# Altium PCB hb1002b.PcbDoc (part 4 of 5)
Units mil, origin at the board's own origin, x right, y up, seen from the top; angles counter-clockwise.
Board outline 2756 x 3549 mil, 2 copper layers (Top Layer, Bottom Layer); 120 components, 136 nets, 498 pads, 328 vias.
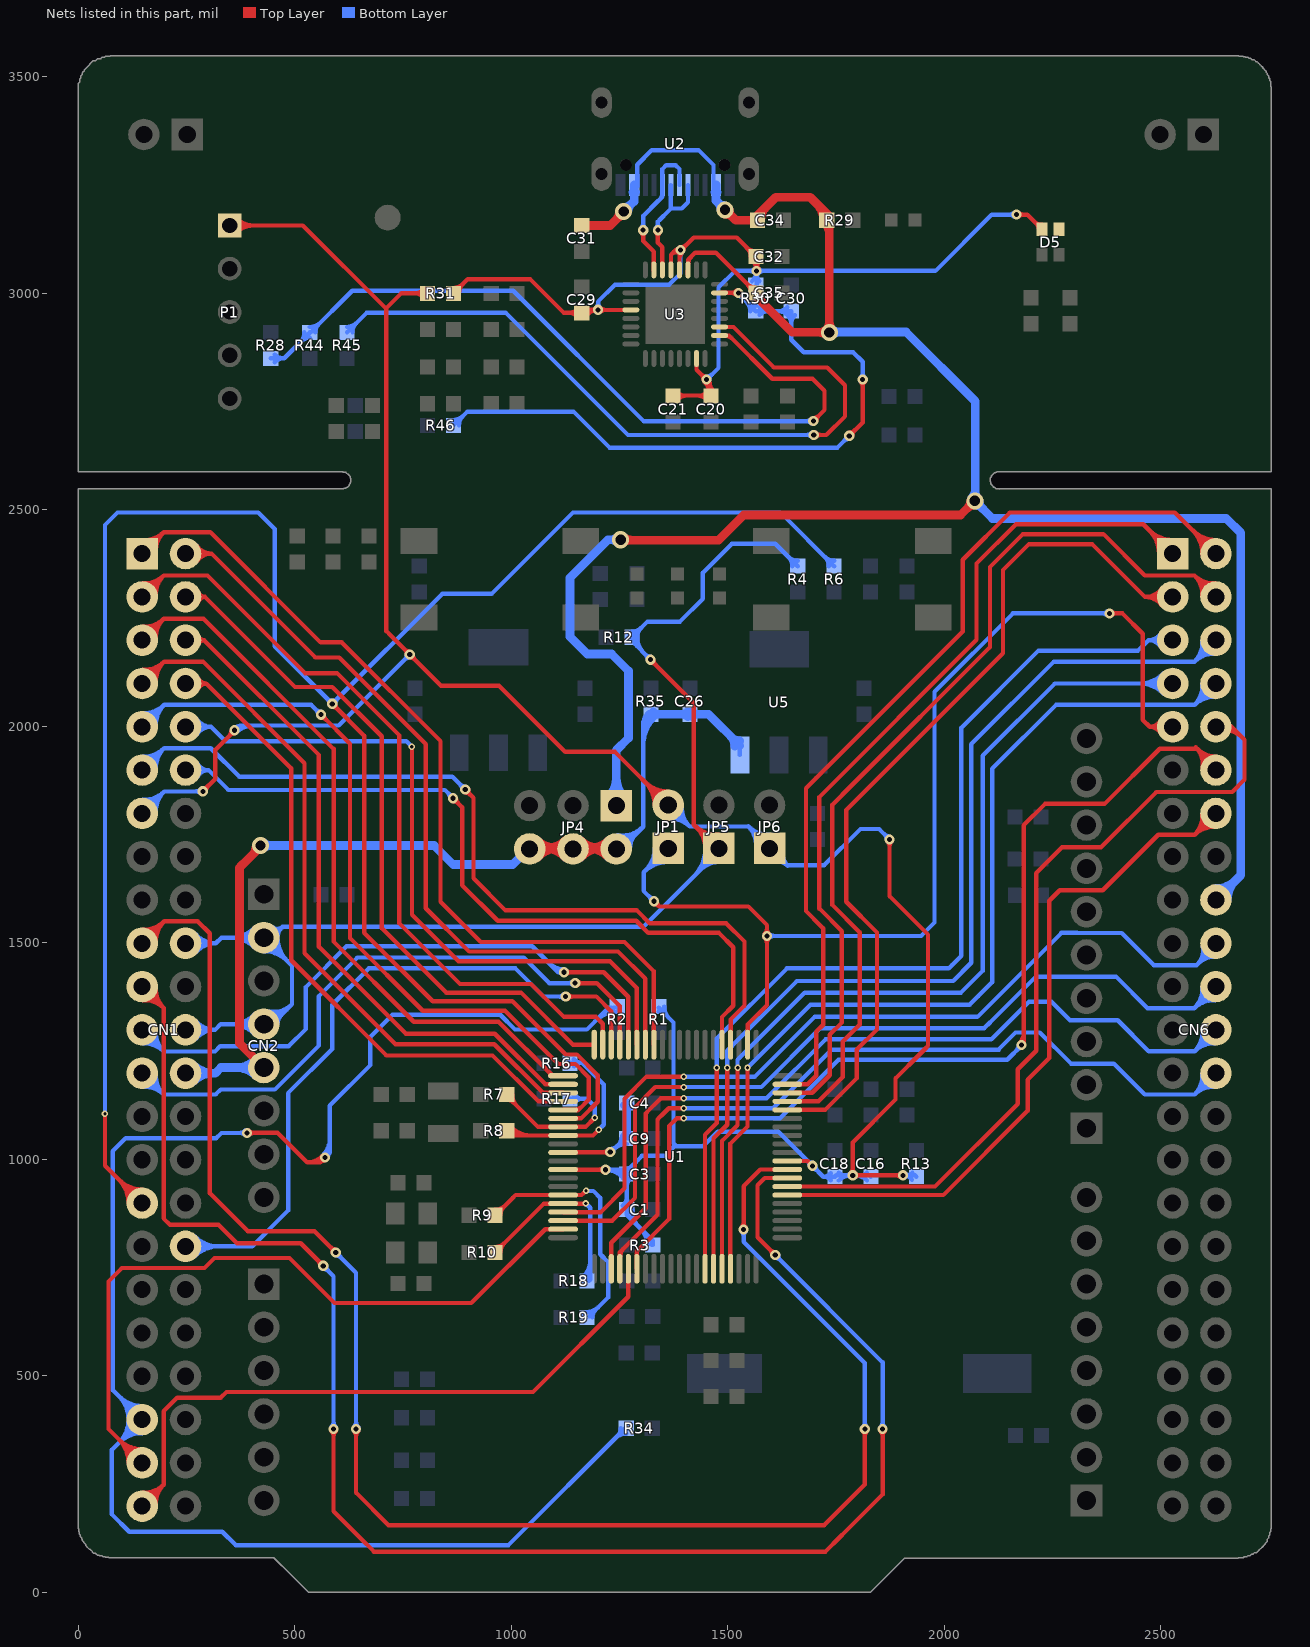
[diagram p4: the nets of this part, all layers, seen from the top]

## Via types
v1: diameter 23.62, hole 11.81, Top Layer to Bottom Layer, tented both sides, 276 vias
v2: diameter 39.37, hole 23.62, Top Layer to Bottom Layer, tented both sides, 27 vias
v3: diameter 15, hole 8, Top Layer to Bottom Layer, tented both sides, 25 vias

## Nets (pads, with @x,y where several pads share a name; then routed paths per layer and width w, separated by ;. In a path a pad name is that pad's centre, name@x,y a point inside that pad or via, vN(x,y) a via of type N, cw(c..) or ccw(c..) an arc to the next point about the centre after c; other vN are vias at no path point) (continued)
PC0: CN6.20 U1.17 | length 2102
  Top Layer w10: U1.17@1120.14,878.05 1120.69,877.5 1206.5,877.5 1262,933 1262,1140 1313,1191 v3(1399,1191)
  Bottom Layer w10: v3@1400,1191 1563,1191 1701,1329 2077,1329 2271,1523 2307.94,1523 2308.36,1522.58 2410.42,1522.58 2484.58,1448.42 2582.88,1448.42 2628,1493.54 CN6.20@2628,1499 ; CN6.20@2597.37,1492 cw(c2554.54,1482.22) 2585.61,1451.15 cw(c2625.38,1411.38) CN6.20@2627.06,1467.6 ; 2598.4,1463.94 ccw(c2575.36,1486.97) CN6.20@2607.12,1494.23 ; 2601.98,1467.52 cw(c2626.33,1443.18) CN6.20@2627.36,1477.59
PC1: CN6.22 U1.18 | length 2111.7
  Top Layer w10: U1.18@1120.14,858.36 1233.36,858.36 1286,911 1286,1120 1333,1167 v3(1399,1167)
  Bottom Layer w10: v3@1400,1167 1578,1167 1714,1303 2093,1303 2114,1324 ; 2101,1311 2114,1324 ; CN6.22@2596.62,1397.4 cw(c2532.85,1394.16) 2578,1349 ; CN6.22@2606.61,1397.91 cw(c2563.13,1395.7) 2593.92,1364.92 cw(c2624.7,1334.13) CN6.22@2626.91,1377.61 ; CN6.22@2626.4,1367.62 ccw(c2623.16,1303.85) 2578,1349 ; CN6.22@2628,1399 2578,1349 ; 2114,1324 2212,1422 2397,1422 2470,1349 2578,1349
PC2: CN1.43 U1.19 | length 1838
  Top Layer w10: CN1.43@116.58,299 ccw(c40.73,299) 94.37,352.63 ccw(c148,406.27) CN1.43@148,330.42 ; CN1.43@126.58,299 ccw(c74.88,299) 111.44,335.56 ccw(c148,372.12) CN1.43@148,320.42 ; CN1.43@148,299 70,377 70,718 101,749 292,749 315,772 488,772 592,668 908,668 1078.68,838.68 U1.19@1120.14,838.68
PC3: CN6.24 U1.23 | length 2075
  Top Layer w10: U1.23@1231.36,747.14 1231.36,807.36 1311,887 1311,1106 ; 1313,1108 1346,1141 v3@1398,1141
  Bottom Layer w10: v3@1400,1141 1562,1141 ; 1582,1141 1562,1141 ; CN6.24@2596.64,1297.13 cw(c2534.73,1293.44) 2578.58,1249.58 ; CN6.24@2606.62,1297.72 cw(c2564.42,1295.21) 2594.31,1265.31 cw(c2624.21,1235.42) CN6.24@2626.72,1277.62 ; CN6.24@2626.13,1267.64 ccw(c2622.44,1205.73) 2578.58,1249.58 ; CN6.24@2628,1299 2578.58,1249.58 ; 1562,1141 1590,1141 1726,1277 2109,1277 2196,1364 2248,1364 2291,1321 2401,1321 2472.42,1249.58 2578.58,1249.58
  other v3: 1399,1141
PC4: CN6.26 U1.24 | length 2161
  Top Layer w10: U1.24@1251.05,747.14 1251.05,785.05 1338,872 1338,946 ; U1.24@1251.95,775.69 cw(c1276.74,775.69) 1259.21,793.21 ; 1338,874 1338,946 ; 1340,1094 1353.5,1107.5 ; v3@1398,1118 1364,1118 1353.5,1107.5 ; 1338,946 1338,1092 1353.5,1107.5
  Bottom Layer w10: v3(1399,1118) 1557,1118 ; 1599,1118 1557,1118 ; 2127,1253 1740,1253 1605,1118 1557,1118 ; 2127,1255 2165,1293 2221,1293 2293,1221 2392,1221 2463.42,1149.58 2578.58,1149.58 ; CN6.26@2596.64,1197.13 cw(c2534.73,1193.44) 2578.58,1149.58 ; CN6.26@2606.62,1197.72 cw(c2564.42,1195.21) 2594.31,1165.31 cw(c2624.21,1135.42) CN6.26@2626.72,1177.62 ; CN6.26@2626.13,1167.64 ccw(c2622.44,1105.73) 2578.58,1149.58 ; CN6.26@2628,1199 2578.58,1149.58
PC5: CN1.45 U1.25 | length 1663.3
  Top Layer w10: CN1.45@148,199 197.42,248.42 ; CN1.45@149.28,220.38 ccw(c151.79,262.58) 181.69,232.69 ccw(c211.58,202.79) CN1.45@169.38,200.28 ; CN1.45@149.87,230.36 ccw(c153.56,292.27) 197.42,248.42 ; CN1.45@179.36,200.87 cw(c241.27,204.56) 197.42,248.42 ; U1.25@1270.73,747.14 1270.73,682.73 1050.58,462.58 342.58,462.58 329.58,449.58 228.7,449.58 197.42,418.3 197.42,248.42
PC6: CN6.12 U1.26 | length 2522.7
  Top Layer w10: U1.26@1290.42,747.14 1290.42,787.42 1365,862 1365,1077 1383,1095 v3@1398,1095 ; v1@2174.18,1268.82 ccw(c2150.49,1292.51) 2184,1292.51 ; v1(2179,1264) 2184,1269 2184,1772 2233,1821 2370.58,1821 2498,1948.42 2584.58,1948.42 ; 2581.58,1951.42 cw(c2542.77,1912.6) CN6.12@2596.98,1903.95 ; 2595.44,1937.56 cw(c2566.67,1908.79) CN6.12@2606.85,1902.38 ; 2601.68,1931.32 ccw(c2628,1957.64) CN6.12@2628,1920.42 ; CN6.12@2628,1899 2628,1905 2584.58,1948.42 ; CN6.12@2628,1930.42 cw(c2628,1991.78) 2584.61,1948.39
  Bottom Layer w10: v3(1399,1095) 1621,1095 1756,1230 2146,1230 2179,1263 v1(2179,1264) ; 2166.67,1250.67 ccw(c2153.33,1264) v1@2172.19,1264 ; 2169.08,1253.08 cw(c2179,1243.16) v1@2179,1257.19
PC7: CN6.14 U1.46 | length 1791.8
  Top Layer w10: U1.46@1637.86,917.42 1882,917.42 1921,917.42 ; 1926.42,917.42 1921,917.42 ; CN6.14@2596.64,1797.13 cw(c2534.73,1793.44) 2578.58,1749.58 ; CN6.14@2606.62,1797.72 cw(c2564.42,1795.21) 2594.31,1765.31 cw(c2624.21,1735.42) CN6.14@2626.72,1777.62 ; CN6.14@2626.13,1767.64 ccw(c2622.44,1705.73) 2578.58,1749.58 ; CN6.14@2628,1799 2578.58,1749.58 ; 1921,917.42 1998.42,917.42 2193,1112 2193,1184 2243,1234 2243,1597 2267.42,1621.42 2366.42,1621.42 2494.58,1749.58 2578.58,1749.58
PC8: CN6.10 U1.47 | length 2110.2
  Top Layer w10: U1.47@1637.86,937.1 1877,937.1 ; 1890,937.1 1877,937.1 ; 2274.58,1720.58 2292,1720.58 ; 2349.58,1720.58 2331,1720.58 ; CN6.10@2625.39,2007.18 cw(c2637.48,1969.32) 2665.58,1997.42 ; CN6.10@2628,1999 2664,1999 2694,1969 2694,1877 2665.42,1848.42 2490.42,1848.42 2362.58,1720.58 2331,1720.58 ; CN6.10@2628.43,1997.65 cw(c2643.1,1951.73) 2677.18,1985.82 ; CN6.10@2631.47,1988.12 cw(c2648.72,1934.14) 2688.79,1974.21 ; 1877,937.1 1979.1,937.1 2170,1128 2170,1208 2213,1251 2213,1661 2272.58,1720.58 2292,1720.58 ; 2292,1720.58 2331,1720.58
PC9: CN6.9 JP1.1 U1.62 | length 2960.7
  Top Layer w10: v1@1330,1589.19 cw(c1330,1572.75) 1341.63,1584.37 cw(c1353.25,1596) v1@1336.81,1596 ; v1(1330,1596) 1342,1584 1548,1584 1591,1541 v1(1591,1516) v1@1591,1511 ; U1.62@1546.32,1264.86 1546.32,1311.32 1591,1356 v1@1591,1510 ; v1@1586.18,1511.18 cw(c1574.56,1499.56) 1591,1499.56 cw(c1607.44,1499.56) v1@1595.82,1511.18 ; v1@1586.18,1520.82 ccw(c1574.56,1532.44) 1591,1532.44 ccw(c1607.44,1532.44) v1@1595.82,1520.82 ; v1(2382,2261) 2412,2261 2459,2214 2459,2015 2475,1999 ; v1@2386.82,2256.18 cw(c2398.44,2244.56) 2398.44,2261 cw(c2398.44,2277.44) v1@2386.82,2265.82 ; CN6.9@2500.44,1983.92 ccw(c2475,1970.01) 2475,1999 ; CN6.9@2500.44,2014.08 cw(c2475,2027.99) 2475,1999 ; CN6.9@2528,1999 2475,1999
  Bottom Layer w10: 1305.95,1662.95 cw(c1363,1605.91) JP1.1@1363,1686.58 ; 1310.78,1667.78 ccw(c1260.56,1718) JP1.1@1331.58,1718 ; 1323.02,1680.02 cw(c1363,1640.05) JP1.1@1363,1696.58 ; v1@1323.19,1596 ccw(c1306.75,1596) 1318.37,1607.63 ccw(c1330,1619.25) v1@1330,1602.81 ; JP1.1@1327.85,1684.85 ccw(c1294.71,1718) JP1.1@1341.58,1718 ; v1(1330,1596) 1306,1620 1306,1663 JP1.1@1362,1719 ; v1@1590,1516 v1(1591,1516) 1947,1516 1978,1547 1978,2080 2159,2261 v1(2382,2261) ; v1@1595.82,1511.18 cw(c1607.44,1499.56) 1607.44,1516 cw(c1607.44,1532.44) v1@1595.82,1520.82 ; v1@2377.18,2256.18 ccw(c2365.56,2244.56) 2365.56,2261 ccw(c2365.56,2277.44) v1@2377.18,2265.82
PC10: CN1.11 U1.64 | length 2191.9
  Top Layer w10: v1@894,1847.19 cw(c894,1830.75) 905.63,1842.37 cw(c917.25,1854) v1@900.81,1854 ; v1(894,1854) 913,1835 913,1649 987,1575 1290.46,1575 1320.46,1545 1497,1545 1539,1503 1539,1355.09 1506.95,1323.04 U1.64@1506.95,1264.86
  Bottom Layer w10: CN1.11@148,1899 198.58,1949.58 ; CN1.11@148.91,1920.4 ccw(c150.8,1965.16) 182.48,1933.48 ccw(c214.16,1901.8) CN1.11@169.4,1899.91 ; CN1.11@149.33,1930.39 ccw(c152.11,1996.05) 198.58,1949.58 ; CN1.11@179.39,1900.33 cw(c245.05,1903.11) 198.58,1949.58 ; v1@887.19,1854 ccw(c870.75,1854) 882.37,1865.63 ccw(c894,1877.25) v1@894,1860.81 ; v1(894,1854) 864.37,1883.63 372.37,1883.63 306.42,1949.58 198.58,1949.58
PC11: CN1.12 U1.65 | length 1889.4
  Top Layer w10: v1@866,1827.19 cw(c866,1810.75) 877.63,1822.37 cw(c889.25,1834) v1@872.81,1834 ; v1(866,1834) 886.81,1813.19 886.81,1633.19 969,1551 1289,1551 1317,1523 1480,1523 1513,1490 1513,1354.54 1487.27,1328.81 U1.65@1487.27,1264.86
  Bottom Layer w10: CN1.12@248,1899 301,1899 ; CN1.12@275.56,1883.92 cw(c301,1870.01) 301,1899 ; CN1.12@275.56,1914.08 ccw(c301,1927.99) 301,1899 ; v1@859.19,1834 ccw(c842.75,1834) 854.37,1845.63 ccw(c866,1857.25) v1@866,1840.81 ; v1(866,1834) 847,1853 347,1853 301,1899
PC12: CN1.9 U1.5 | length 2047.9
  Top Layer w10: v1@561,2020.19 cw(c561,2003.75) 572.63,2015.37 cw(c584.25,2027) v1@567.81,2027 ; v1@562,2026 628,1960 628,1511 796,1343 986,1343 1109,1220 1148.43,1220 1179,1189.43 1179,1137.53 1156.52,1115.05 ; U1.5@1120.14,1114.27 1120.92,1115.05 1156.52,1115.05 ; U1.5@1148.69,1115.17 ccw(c1148.69,1134.38) 1162.27,1120.8 ; U1.5@1149.3,1114.93 ccw(c1152.85,1118.71) 1156.52,1115.05
  Bottom Layer w10: CN1.9@148,1999 198.58,2049.58 ; CN1.9@148.91,2020.4 ccw(c150.8,2065.16) 182.48,2033.48 ccw(c214.16,2001.8) CN1.9@169.4,1999.91 ; CN1.9@149.33,2030.39 ccw(c152.11,2096.05) 198.58,2049.58 ; CN1.9@179.39,2000.33 cw(c245.05,2003.11) 198.58,2049.58 ; v1@554.19,2027 ccw(c537.75,2027) 549.37,2038.63 ccw(c561,2050.25) v1@561,2033.81 ; v1(561,2027) 538.42,2049.58 198.58,2049.58
PC13: CN1.31 R6.1 U1.6 | length 5649.8
  Top Layer w10: v3@62,1104 62,985 CN1.31@148,899 ; CN1.31@116.58,899 ccw(c40.73,899) 94.37,952.63 ccw(c148,1006.27) CN1.31@148,930.42 ; CN1.31@126.58,899 ccw(c74.88,899) 111.44,935.56 ccw(c148,972.12) CN1.31@148,920.42 ; v1@587,2045.19 cw(c587,2028.75) 598.63,2040.37 cw(c610.25,2052) v1@593.81,2052 ; v1(587,2052) 661,1978 661,1885 ; 661,1945 661,1885 ; U1.6@1120.14,1094.58 1161.51,1094.58 1200,1133.08 1200,1193.89 1151.89,1242 1126,1242 1003,1365 819,1365 661,1523 661,1885
  Bottom Layer w10: v3(62,1104.99) 62,2465 91,2494 416,2494 454,2456 454,2185 v1(587,2052) 841,2306 955,2306 1143,2494 1622,2494 R6.1@1746,2370 ; v1@580.19,2052 ccw(c563.75,2052) 575.37,2063.63 ccw(c587,2075.25) 587,2058.81 ccw(c587,2075.25) 598.63,2063.63 ccw(c610.25,2052) v1@593.81,2052 ; R6.1@1733.5,2370 ccw(c1703.32,2370) 1724.66,2391.34 ccw(c1746,2412.68) R6.1@1746,2382.5
PC14: R7.1 R17.2 U1.7 | length 425.9
  Top Layer w10: R7.1@990,1137.5 cw(c990,1114.82) 1006.04,1130.86 ; R7.1@993.9,1143 1062,1074.9 U1.7@1120.14,1074.9 1171.9,1074.9 v3@1192,1095 ; R7.1@1002.5,1150 ccw(c1040.17,1150) 1013.53,1123.36
  Bottom Layer w10: R17.2@1129,1137 R17.2@1136,1137 ; R17.2@1136,1140 1175,1140 1193,1122 v3@1193,1097 ; R17.2@1144.84,1131.16 cw(c1166.18,1109.82) 1166.18,1140 cw(c1166.18,1170.18) R17.2@1144.84,1148.84
  other v3: 1193,1096
PC15: R8.1 R16.2 U1.8 | length 570.2
  Top Layer w10: R8.1@990.21,1055.21 U1.8@1120.14,1055.21 1159,1055.21 ; R8.1@991.77,1067.77 ccw(c1022.08,1098.08) 1022.08,1055.21 ; R8.1@998.84,1074.84 ccw(c1046.22,1122.22) 1046.22,1055.21 ; 1169.21,1055.21 1159,1055.21 ; v3(1202,1068) 1189.21,1055.21 1159,1055.21
  Bottom Layer w10: R16.2@1130,1223 1132,1223 1164,1223 ; R16.2@1144.84,1230.84 ccw(c1163.76,1249.76) 1163.76,1223 ; R16.2@1145.78,1214.22 cw(c1164,1199.72) 1164,1223 ; v3(1202,1068) 1214,1080 1214,1173 1164,1223
PD0: CN1.21 U1.48 | length 4302.2
  Top Layer w10: CN1.21@148,1399 197.42,1349.58 ; CN1.21@149.28,1377.62 cw(c151.79,1335.42) 181.69,1365.31 cw(c211.58,1395.21) CN1.21@169.38,1397.72 ; CN1.21@149.87,1367.64 cw(c153.56,1305.73) 197.42,1349.58 ; CN1.21@179.36,1397.13 ccw(c241.27,1393.44) 197.42,1349.58 ; v1@559.19,754 ccw(c542.75,754) 554.37,765.63 ccw(c566,777.25) v1@566,760.81 ; v1(566,754) 514,806 367,806 324,849 212,849 197.42,863.58 197.42,1349.58 ; v1@585.01,372.18 cw(c573.38,360.56) 589.82,360.56 cw(c606.27,360.56) v1@594.64,372.18 ; v1(589.82,377) 589.82,187.18 636.5,140.5 ; 665,112 636.5,140.5 ; v1@1603.19,779 ccw(c1586.75,779) 1598.37,790.63 ccw(c1610,802.25) v1@1610,785.81 ; v1(1610,779) 1569,820 1569,940 1585.79,956.79 U1.48@1637.86,956.79 ; 1744,112 1787.5,155.5 ; v1@1853.18,372.18 cw(c1841.56,360.56) 1858,360.56 cw(c1874.44,360.56) v1@1862.82,372.18 ; v1(1858,377) 1858,226 1787.5,155.5 ; 636.5,140.5 683,94 1726,94 1787.5,155.5
  Bottom Layer w10: v1@566,747.19 cw(c566,730.75) 577.63,742.37 cw(c589.25,754) v1@572.81,754 ; v1(566,754) 589.82,730.18 v1(589.82,377) ; v1@585.01,381.82 ccw(c573.38,393.44) 589.82,393.44 ccw(c606.27,393.44) v1@594.64,381.82 ; v1@1610,772.19 cw(c1610,755.75) 1621.63,767.37 cw(c1633.25,779) v1@1616.81,779 ; v1(1610,779) 1858,531 v1(1858,377) ; v1@1853.18,381.82 ccw(c1841.56,393.44) 1858,393.44 ccw(c1874.44,393.44) v1@1862.82,381.82
PD1: CN1.19 U1.49 | length 4288.3
  Top Layer w10: CN1.19@148,1499 199,1550 ; CN1.19@148.78,1520.4 ccw(c150.43,1566.1) 182.76,1533.76 ccw(c215.1,1501.43) CN1.19@169.4,1499.78 ; CN1.19@149.14,1530.4 ccw(c151.57,1597.42) 199,1550 ; CN1.19@179.4,1500.14 cw(c246.42,1502.57) 199,1550 ; v1@588.19,785 ccw(c571.75,785) 583.37,796.63 ccw(c595,808.25) v1@595,791.81 ; v1@593,783 v1(595,785) 546,834 392,834 304,922 304,1522 276,1550 199,1550 ; v1@637.01,372.18 cw(c625.38,360.56) 641.82,360.56 cw(c658.27,360.56) v1@646.64,372.18 ; v1(641.82,377) 641.82,230.18 717,155 1723,155 1817,249 v1(1817,377) ; v1@1532.18,842.82 ccw(c1520.56,854.44) 1537,854.44 ccw(c1553.44,854.44) v1@1541.82,842.82 ; v1(1537,838) 1537,938 1575.47,976.47 U1.49@1637.86,976.47 ; v1@1812.18,372.18 cw(c1800.56,360.56) 1817,360.56 cw(c1833.44,360.56) v1@1821.82,372.18
  Bottom Layer w10: v1@595,778.19 cw(c595,761.75) 606.63,773.37 cw(c618.25,785) v1@601.81,785 ; v1(595,785) 641.82,738.18 v1(641.82,377) ; v1@637.01,381.82 ccw(c625.38,393.44) 641.82,393.44 ccw(c658.27,393.44) v1@646.64,381.82 ; v1@1532.18,833.18 cw(c1520.56,821.56) 1537,821.56 cw(c1553.44,821.56) v1@1541.82,833.18 ; v1@1533.51,832.15 cw(c1529.84,826) 1537,826 ; v1(1537,838) v1@1537,827 ; v1@1540.49,832.15 ccw(c1544.16,826) 1537,826 ; v1@1812.18,381.82 ccw(c1800.56,393.44) 1817,393.44 ccw(c1833.44,393.44) v1@1821.82,381.82 ; v1(1817,377) 1817,529.59 1537,809.59 v1@1537,827 ; 1537,826 v1@1537,827
PD2: CN1.10 U1.75 | length 1781
  Top Layer w10: v3(771,1953) 771,1565 878.5,1457.5 1228.5,1457.5 1290.42,1395.58 U1.75@1290.42,1264.86
  Bottom Layer w10: CN1.10@248,1999 307,1999 ; CN1.10@265.77,1987.05 cw(c288.22,1971.95) 288.22,1999 cw(c288.22,2026.05) CN1.10@265.77,2010.95 ; CN1.10@274.07,1981.46 cw(c307,1959.31) 307,1999 ; CN1.10@274.07,2016.54 ccw(c307,2038.69) 307,1999 ; v3(771,1953) 758,1966 340,1966 307,1999
PD3: CN1.23 U1.76 | length 1741.8
  Top Layer w10: v1@1122,1434 v1(1122,1432) 1214,1432 1270.73,1375.27 U1.76@1270.73,1264.86 ; v1@1126.82,1427.18 cw(c1138.44,1415.56) 1138.44,1432 cw(c1138.44,1448.44) v1@1126.82,1436.82
  Bottom Layer w10: CN1.23@149.09,1277.61 cw(c151.3,1234.13) 182.08,1264.92 cw(c212.87,1295.7) CN1.23@169.39,1297.91 ; CN1.23@149.17,1299 CN1.23@148,1299 198,1249 ; CN1.23@149.6,1267.62 cw(c152.84,1203.85) 198,1249 ; CN1.23@179.38,1297.4 ccw(c243.15,1294.16) 198,1249 ; 1088.18,1452.82 ccw(c1122,1486.64) v1@1122,1438.81 ; 1105.25,1435.75 ccw(c1122,1452.5) v1@1122,1428.81 ; v1@1116.4,1428.12 ccw(c1109,1423) 1109,1432 ; v1@1116.4,1435.88 cw(c1109,1441) 1109,1432 ; v1(1122,1432) 1109,1432 ; 198,1249 316,1249 328.42,1261.42 486.42,1261.42 526,1301 526,1398 620,1492 1049,1492 1109,1432
PD4: CN1.25 U1.77 | length 1689
  Top Layer w10: v1@1149,1406 v1(1148,1407) 1198.05,1407 1199.05,1406 1251.05,1354 U1.77@1251.05,1264.86 ; v1@1152.82,1402.18 cw(c1164.44,1390.56) 1164.44,1407 cw(c1164.44,1423.44) v1@1152.82,1411.82
  Bottom Layer w10: CN1.25@148,1199 197.42,1149.58 ; CN1.25@149.28,1177.62 cw(c151.79,1135.42) 181.69,1165.31 cw(c211.58,1195.21) CN1.25@169.38,1197.72 ; CN1.25@149.87,1167.64 cw(c153.56,1105.73) 197.42,1149.58 ; CN1.25@179.36,1197.13 ccw(c241.27,1193.44) 197.42,1149.58 ; v1@1143.18,1402.18 ccw(c1131.56,1390.56) 1131.56,1407 ccw(c1131.56,1423.44) v1@1143.18,1411.82 ; v1@1146,1405 v1(1148,1407) 1088,1407 1029,1466 645,1466 556,1377 556,1263 454.42,1161.42 329.42,1161.42 317.58,1149.58 197.42,1149.58
PD5: CN1.34 U1.78 | length 1897.5
  Top Layer w10: v1(1126,1376) 1197,1376 1231.36,1341.64 U1.78@1231.36,1264.86 1231.36,1324.64 ; v1@1130.82,1371.18 cw(c1142.44,1359.56) 1142.44,1376 cw(c1142.44,1392.44) v1@1130.82,1380.82
  Bottom Layer w10: CN1.34@248,799 402,799 485,882 485,1153 587,1255 587,1357 671,1441 1010,1441 1075,1376 v1(1126,1376) ; CN1.34@263.14,783.86 cw(c299.71,747.29) 299.71,799 cw(c299.71,850.71) CN1.34@263.14,814.14 ; CN1.34@270.22,776.78 cw(c323.85,723.15) 323.85,799 cw(c323.85,874.85) CN1.34@270.22,821.22 ; v1@1121.18,1371.18 ccw(c1109.56,1359.56) 1109.56,1376 ccw(c1109.56,1392.44) v1@1121.18,1380.82
PD6: CN1.5 U1.1 | length 1876.7
  Top Layer w10: CN1.5@148,2199 197.42,2248.42 ; CN1.5@149.28,2220.38 ccw(c151.79,2262.58) 181.69,2232.69 ccw(c211.58,2202.79) CN1.5@169.38,2200.28 ; CN1.5@149.87,2230.36 ccw(c153.56,2292.27) 197.42,2248.42 ; CN1.5@179.36,2200.87 cw(c241.27,2204.56) 197.42,2248.42 ; 1086.95,1202.05 cw(c1077.9,1193.01) U1.1@1090.69,1193.01 ; U1.1@1120.14,1193.01 1095.99,1193.01 971,1318 775,1318 590,1503 590,1948 289.58,2248.42 197.42,2248.42
PD7: CN1.6 U1.2 | length 1591.1
  Top Layer w10: CN1.6@248,2199 291,2199 ; CN1.6@277.93,2189.45 cw(c291,2185.28) 291,2199 ; CN1.6@277.93,2208.55 ccw(c291,2212.72) 291,2199 ; U1.2@1120.14,1173.32 1079.13,1173.32 962.46,1290 757,1290 556,1491 556,1934 291,2199
PD8: CN1.7 U1.3 | length 1845.8
  Top Layer w10: CN1.7@148,2099 198.58,2149.58 ; CN1.7@148.91,2120.4 ccw(c150.8,2165.16) 182.48,2133.48 ccw(c214.16,2101.8) CN1.7@169.4,2099.91 ; CN1.7@149.33,2130.39 ccw(c152.11,2196.05) 198.58,2149.58 ; CN1.7@179.39,2100.33 cw(c245.05,2103.11) 198.58,2149.58 ; U1.3@1120.14,1153.64 1073.36,1153.64 961,1266 733,1266 523,1476 523,1915 288.42,2149.58 198.58,2149.58
PD9: CN1.8 U1.4 | length 1580
  Top Layer w10: CN1.8@248,2099 296,2099 ; CN1.8@276.79,2086.43 cw(c296,2078.04) 296,2099 ; CN1.8@276.79,2111.57 ccw(c296,2119.96) 296,2099 ; U1.4@1120.14,1133.95 1063,1133.95 956.95,1240 712,1240 492,1460 492,1903 296,2099
PD10: CN6.5 U1.34 | length 2481.1
  Top Layer w10: U1.34@1447.9,747.14 1447.9,1056.9 1475,1084 v3(1475,1211.65)
  Bottom Layer w10: v3(1475,1211.65) 1475,1279 1637,1441 1729,1441 ; 1674,1441 1729,1441 ; 2013,1443 2023.5,1453.5 ; 2018,1448 2023.5,1453.5 ; CN6.5@2501.19,2182.63 ccw(c2472,2164.8) 2472,2199 ; CN6.5@2501.19,2215.37 cw(c2472,2233.2) 2472,2199 ; CN6.5@2509.72,2187.84 ccw(c2489.83,2175.69) 2489.83,2199 ccw(c2489.83,2222.31) CN6.5@2509.72,2210.16 ; CN6.5@2528,2199 2472,2199 ; 1729,1441 2011,1441 2023.5,1453.5 ; 2023.5,1453.5 2040,1470 2040,1997 2218,2175 2448,2175 2472,2199
PD11: CN6.6 U1.35 | length 2536.8
  Top Layer w10: U1.35@1467.58,747.14 1467.58,1048.58 1499,1080 v3(1499,1211.65)
  Bottom Layer w10: v3(1499,1211.65) 1499,1251 1524,1276 ; 1509,1261 1524,1276 ; CN6.6@2596.64,2197.13 cw(c2534.73,2193.44) 2578.58,2149.58 ; CN6.6@2606.62,2197.72 cw(c2564.42,2195.21) 2594.31,2165.31 cw(c2624.21,2135.42) CN6.6@2626.72,2177.62 ; CN6.6@2626.13,2167.64 ccw(c2622.44,2105.73) 2578.58,2149.58 ; CN6.6@2628,2193.98 CN6.6@2628,2199 2578.58,2149.58 ; 1524,1276 1660,1412 2021,1412 2063,1454 2063,1959 2253.58,2149.58 2578.58,2149.58
PD12: CN6.7 U1.36 | length 2355.3
  Top Layer w10: U1.36@1487.27,747.14 1487,747.41 1487,1042.54 1523,1078.54 v3@1523,1211 ; v3@1522.5,1211 v3@1522.5,1212
  Bottom Layer w10: v3@1523,1211 v3(1523,1211.65) 1523,1230 1678,1385 2039,1385 2089,1435 2089,1932 2256,2099 CN6.7@2528,2099 ; CN6.7@2505.78,2076.78 ccw(c2452.15,2023.15) 2452.15,2099 ccw(c2452.15,2174.85) CN6.7@2505.78,2121.22 ; CN6.7@2512.86,2083.86 ccw(c2476.29,2047.29) 2476.29,2099 ccw(c2476.29,2150.71) CN6.7@2512.86,2114.14
PD13: CN6.8 U1.37 | length 2499.1
  Top Layer w10: U1.37@1506.95,747.14 1506.5,747.59 1506.5,1036.5 1546,1076 v3(1546,1211.65)
  Bottom Layer w10: v3(1546,1211.65) 1691.35,1357 2059,1357 2079,1377 ; 2061,1359 2079,1377 ; 2467,2049.58 2524,2049.58 ; CN6.8@2596.64,2097.13 cw(c2534.73,2093.44) 2578.58,2049.58 ; CN6.8@2606.62,2097.72 cw(c2564.42,2095.21) 2594.31,2065.31 cw(c2624.21,2035.42) CN6.8@2626.72,2077.62 ; CN6.8@2626.13,2067.64 ccw(c2622.44,2005.73) 2578.58,2049.58 ; CN6.8@2648.99,2099 CN6.8@2628,2099 2578.58,2049.58 ; 2079,1377 2111,1409 2111,1902 2258.58,2049.58 2524,2049.58 ; 2524,2049.58 2578.58,2049.58
PD14: CN6.3 U1.56 | length 2182.3
  Top Layer w10: U1.56@1637.86,1114.27 1725.27,1114.27 1798,1187 1798,1253 1845,1300 1845,1524 1774,1595 1774,1807 2136,2169 2136,2361 2196,2421 2342,2421 2464,2299 ; CN6.3@2503.14,2279.79 ccw(c2464,2249.53) 2464,2299 ; CN6.3@2503.14,2318.21 cw(c2464,2348.47) 2464,2299 ; CN6.3@2511.06,2285.9 ccw(c2484.37,2265.28) 2484.37,2299 ccw(c2484.37,2332.72) CN6.3@2511.06,2312.1 ; CN6.3@2528,2299 2464,2299
PD15: CN6.4 U1.57 | length 2342.8
  Top Layer w10: U1.57@1637.86,1133.95 1709.95,1133.95 1766,1190 1766,1272 1805,1311 1805,1524.46 1742,1587.46 1742,1819 1787,1864 ; 1766,1843 1787,1864 ; CN6.4@2596.63,2300.79 ccw(c2534.2,2304.36) 2578.42,2348.58 ; CN6.4@2606.62,2300.22 ccw(c2564.06,2302.65) 2594.2,2332.8 ccw(c2624.35,2362.94) CN6.4@2626.78,2320.38 ; CN6.4@2626.21,2330.37 cw(c2622.64,2392.8) 2578.42,2348.58 ; CN6.4@2628,2299 2578.42,2348.58 ; 1787,1864 2106,2183 2106,2368 2182,2444 2368,2444 2463.42,2348.58 2578.42,2348.58
PE0: CN6.1 U1.58 | length 2199.6
  Top Layer w10: U1.58@1637.86,1153.64 1695.64,1153.64 1736,1194 1736,1288 1764,1316 1764,1527 1712,1579 1712,1837 2075,2200 2075,2376 2166,2467 2460,2467 CN6.1@2528,2399 ; CN6.1@2496.58,2399 ccw(c2420.73,2399) 2474.37,2452.63 ccw(c2528,2506.27) CN6.1@2528,2430.42 ; CN6.1@2506.58,2399 ccw(c2454.88,2399) 2491.44,2435.56 ccw(c2528,2472.12) CN6.1@2528,2420.42
PE1: CN6.2 U1.59 | length 2351.6
  Top Layer w10: U1.59@1637.86,1173.32 1685.32,1173.32 1705,1193 1705,1295 1721,1311 1721,1533.46 1714.73,1539.73 ; 1705,1549.46 1714.73,1539.73 ; 1705,1881 1724.5,1900.5 ; CN6.2@2596.58,2399 ccw(c2520.73,2399) 2574.37,2452.63 ccw(c2628,2506.27) CN6.2@2628,2430.42 ; CN6.2@2606.58,2399 ccw(c2554.88,2399) 2591.44,2435.56 ccw(c2628,2472.12) CN6.2@2628,2420.42 ; CN6.2@2628,2399 2533,2494 2152,2494 2043,2385 2043,2219 1724.5,1900.5 ; 1714.73,1539.73 1681,1573.46 1681,1857 1724.5,1900.5
PE2: CN1.1 U1.73 | length 2185.8
  Top Layer w10: CN1.1@148,2399 197.5,2448.5 ; CN1.1@149.25,2420.38 ccw(c151.72,2462.76) 181.74,2432.74 ccw(c211.76,2402.72) CN1.1@169.38,2400.25 ; CN1.1@149.83,2430.36 ccw(c153.46,2492.53) 197.5,2448.5 ; CN1.1@179.36,2400.83 cw(c241.53,2404.46) 197.5,2448.5 ; U1.73@1329.79,1264.86 1329.19,1265.46 1329.19,1434.81 1262,1502 930,1502 837,1595 837,1966 609,2194 560,2194 305.5,2448.5 197.5,2448.5
PE3: CN1.2 U1.74 | length 1977.9
  Top Layer w10: CN1.2@248,2399 308,2399 ; CN1.2@265.6,2386.8 cw(c288.9,2370.65) 288.9,2399 cw(c288.9,2427.35) CN1.2@265.6,2411.2 ; CN1.2@273.82,2381.1 cw(c308,2357.42) 308,2399 ; CN1.2@273.82,2416.9 ccw(c308,2440.58) 308,2399 ; U1.74@1310.1,1264.86 1310.1,1416.9 1247,1480 903,1480 803,1580 803,1959 603,2159 548,2159 308,2399
PE4: CN1.3 U1.79 | length 1991.8
  Top Layer w10: CN1.3@148,2299 197.42,2348.42 ; CN1.3@149.28,2320.38 ccw(c151.79,2362.58) 181.69,2332.69 ccw(c211.58,2302.79) CN1.3@169.38,2300.28 ; CN1.3@149.87,2330.36 ccw(c153.56,2392.27) 197.42,2348.42 ; CN1.3@179.36,2300.87 cw(c241.27,2304.56) 197.42,2348.42 ; U1.79@1211.68,1264.86 1211.68,1313.32 1196,1329 1122,1329 1046,1405 882,1405 742,1545 742,1979 598,2123 524,2123 298.58,2348.42 197.42,2348.42
PE5: CN1.4 U1.80 | length 1672.1
  Top Layer w10: CN1.4@248,2299 293,2299 ; CN1.4@277.49,2288.17 cw(c293,2282.48) 293,2299 ; CN1.4@277.49,2309.83 ccw(c293,2315.52) 293,2299 ; U1.80@1191.99,1264.86 1143.14,1264.86 1023,1385 850,1385 701,1534 701,1977 587,2091 501,2091 293,2299
PF0: R9.2 R19.2 U1.15 | length 788.7
  Top Layer w10: R9.2@963,871 964,871 1004,911 ; R9.2@964.86,883.36 ccw(c967.85,903.15) 982,889 ; R9.2@975.48,871.77 cw(c997.85,873.15) 982,889 ; 1167.04,922.03 cw(c1173,916.07) v3@1173,924.5 ; v3@1172,926 1171.01,926 1162.43,917.42 U1.15@1120.14,917.42 1010.42,917.42 1004,911 ; 982,889 1004,911 ; R9.2@963,883.5 ccw(c963,916.09) 986.05,893.05 cw(c963,916.09) R9.2@963,883.5 ; R9.2@975.5,871 cw(c1003.26,871) 983.63,890.63 ccw(c1003.26,871) R9.2@975.5,871
  Bottom Layer w10: v3(1173,927) 1190,927 1206,911 1206,781 1224,763 1224,681 R19.2@1180,637 ; R19.2@1175,647.5 ccw(c1175,684.92) 1201.46,658.46 ; R19.2@1187.5,635 cw(c1210.43,635) 1194.22,651.22
PF1: R10.2 R18.2 U1.16 | length 566.6
  Top Layer w10: R10.2@963,785 1019.5,841.5 1075.73,897.73 U1.16@1120.14,897.73 v3@1171.73,897.73 ; R10.2@963,797.5 ccw(c963,827.68) 984.34,806.34 ccw(c1005.68,785) R10.2@975.5,785
  Bottom Layer w10: R18.2@1166.16,727.84 ccw(c1125.51,768.49) 1183,768.49 ; v3@1172,895.5 cw(c1172,887.05) 1177.97,893.03 ; v3@1172,899 1183,888 1183,722 R18.2@1180,719 ; R18.2@1173.23,720.77 ccw(c1149.65,744.35) 1183,744.35
  other v3: 1172,898
PRG_NRST: C30.1 R30.2 R46.1 U3.7 | length 1982.2
  Top Layer w10: U3.7@1481.36,3001.21 v1@1524.79,3001.21 ; 1508.04,3001.21 cw(c1508.04,2984.04) v1@1520.18,2996.18 ; 1509.07,3001.21 ccw(c1509.07,3016.93) v1@1520.18,3005.82 ; v1(1781,2671) 1812,2702 v1@1812,2800 ; v1@1781,2677.81 ccw(c1781,2694.25) 1792.63,2682.63 ccw(c1804.25,2671) v1@1787.81,2671 ; v1@1807.18,2796.18 cw(c1795.56,2784.56) 1812,2784.56 cw(c1828.44,2784.56) v1@1816.82,2796.18
  Bottom Layer w10: R46.1@867,2695 899,2727 1144,2727 1227.19,2643.81 1753.81,2643.81 1780.5,2670.5 v1@1781.5,2670.5 ; R46.1@867,2707.5 ccw(c867,2737.68) 888.34,2716.34 ccw(c909.68,2695) R46.1@879.5,2695 ; v1@1525,2994.19 cw(c1525,2982.57) 1533.21,2990.79 ; v1@1525,2999 R30.2@1565,2959 C30.1@1647,2959 1647,2893 1676,2864 1790,2864 1812,2842 v1(1812,2801) ; v1@1531.81,3001 ccw(c1553.08,3001) 1538.04,2985.96 ; R30.2@1552.5,2959 ccw(c1522.32,2959) 1543.66,2980.34 ccw(c1565,3001.68) R30.2@1565,2971.5 ; R30.2@1573.84,2950.16 cw(c1595.18,2928.82) 1595.18,2959 cw(c1595.18,2989.18) R30.2@1573.84,2967.84 ; C30.1@1638.16,2967.84 cw(c1616.82,2989.18) 1616.82,2959 cw(c1616.82,2928.82) 1638.16,2950.16 cw(c1616.82,2928.82) 1647,2928.82 cw(c1677.18,2928.82) C30.1@1655.84,2950.16 ; v1@1774.19,2671 cw(c1757.75,2671) 1769.37,2659.37 cw(c1781,2647.75) v1@1781,2664.19 ; v1@1807.18,2805.82 ccw(c1795.56,2817.44) 1812,2817.44 ccw(c1828.44,2817.44) v1@1816.82,2805.82
  other v1: 1525,3001
PRG_SWCLK: R28.2 R44.1 U3.2 | length 2040.8
  Top Layer w10: U3.2@1481.36,2902.79 1503.21,2902.79 1603,2803 1696,2803 1724,2775 1724,2731 v1(1698,2705) ; U3.2@1495.54,2902.28 cw(c1495.54,2882.51) 1509.51,2896.49 ; U3.2@1495.64,2902.29 cw(c1498.3,2890.2) 1507.05,2898.95 ; v1@1698,2711.81 ccw(c1698,2728.25) 1709.63,2716.63 ccw(c1721.25,2705) v1@1704.81,2705
  Bottom Layer w10: R28.2@445,2850 476,2850 535,2909 R44.1@535,2910 537,2910 633,3006 1005,3006 1306,2705 v1@1697.77,2705 ; R28.2@453.84,2841.16 cw(c475.18,2819.82) 475.18,2850 cw(c475.18,2880.18) R28.2@453.84,2858.84 ; 512.96,2886.96 ccw(c489.91,2910) R44.1@522.5,2910 ; 515.37,2889.37 cw(c535,2869.74) R44.1@535,2897.5 ; R44.1@535,2922.5 ccw(c535,2957.51) 559.75,2932.75 ; R44.1@547.5,2910 cw(c572.85,2910) 554.93,2927.93 ; v1@1693.18,2700.18 ccw(c1681.56,2688.56) 1681.56,2705 ccw(c1681.56,2721.44) v1@1693.18,2709.82
PRG_SWDIO: R45.1 U3.3 | length 1821.6
  Top Layer w10: U3.3@1479.39,2922.47 1513.53,2922.47 1607,2829 1730,2829 1771,2788 1771,2716 1728,2673 v1(1699,2673) ; v1@1703.82,2668.18 cw(c1715.44,2656.56) 1715.44,2673 cw(c1715.44,2689.44) v1@1703.82,2677.82
  Bottom Layer w10: R45.1@621,2910 666,2955 988,2955 1270,2673 v1(1699,2673) ; R45.1@621,2922.5 ccw(c621,2952.68) 642.34,2931.34 ccw(c663.68,2910) R45.1@633.5,2910 ; v1@1694.18,2668.18 ccw(c1682.56,2656.56) 1682.56,2673 ccw(c1682.56,2689.44) v1@1694.18,2677.82
USB_DM: U2.A7 U2.B7 U3.15 | length 413.1
  Top Layer w10: v1@1300.18,3141.18 cw(c1288.56,3129.56) 1305,3129.56 cw(c1321.44,3129.56) v1@1309.82,3141.18 ; v1(1305,3146) 1305,3121 1329.79,3096.21 U3.15@1329.79,3052.39
  Bottom Layer w10: v1@1300.18,3150.82 ccw(c1288.56,3162.44) 1305,3162.44 ccw(c1321.44,3162.44) v1@1309.82,3150.82 ; v1(1305,3146) 1305,3179 1339.81,3213.81 1340.17,3213.81 1349.39,3223.03 U2.B7@1349.39,3250.4 1349.39,3287.39 1358,3296 1380,3296 1388.76,3287.24 U2.A7@1388.76,3250.4 ; 1344.02,3217.66 ccw(c1332.94,3228.73) U2.B7@1348.49,3230.61
USB_DP: U2.A6 U2.B6 U3.14 | length 383.6
  Top Layer w10: v1@1334.18,3141.18 cw(c1322.56,3129.56) 1339,3129.56 cw(c1355.44,3129.56) v1@1343.82,3141.18 ; v1(1339,3146) 1339,3117 1349.47,3106.53 U3.14@1349.47,3052.39
  Bottom Layer w10: v1@1334.18,3150.82 ccw(c1322.56,3162.44) 1339,3162.44 ccw(c1355.44,3162.44) v1@1343.82,3150.82 ; v1(1339,3146) 1339,3166 1364.5,3191.5 ; 1342,3169 1364.5,3191.5 ; U2.A6@1369.08,3250.4 1369.08,3196.08 ; U2.B6@1408.45,3250.4 1408.45,3210.45 1394.08,3196.08 1369.08,3196.08 ; 1364.5,3191.5 1369.08,3196.08
VBAT: CN1.41 R2.1 R34.1 | length 4484.7
  Top Layer w10: v1@390.42,1061.42 460.58,1061.42 529,993 ; v1@394.82,1056.18 cw(c407.45,1043.55) 407.45,1061.42 ; v1@394.82,1065.82 ccw(c405.44,1076.44) 405.44,1061.42 ; 552.02,993 ccw(c552.02,1020.79) v1@572.33,1001.82 ; 557.5,992.5 cw(c568.88,981.12) v1@569.67,997.2 ; 559.08,994.08 ccw(c549.16,1004) v1@563.19,1004 ; v1@565.02,1008.65 cw(c529,1042.28) 529,993 ; v1@569,1004 558,993 529,993
  Bottom Layer w10: CN1.41@148,367.58 ccw(c148,291.73) 94.37,345.37 ccw(c40.73,399) 116.58,399 ccw(c40.73,399) 94.37,452.63 ccw(c148,506.27) CN1.41@148,430.42 ; CN1.41@148,377.58 ccw(c148,325.88) 111.44,362.44 ccw(c74.88,399) 126.58,399 ccw(c74.88,399) 111.44,435.56 ccw(c148,472.12) CN1.41@148,420.42 ; v1@385.18,1056.18 ccw(c373.56,1044.56) 373.56,1061 ccw(c373.56,1077.44) v1@385.18,1065.82 ; v1(390,1061) 331,1061 319,1049 110,1049 80,1019 80,467 CN1.41@148,399 78,329 78,180 118,140 333,140 364,109 379,109 ; 412,109 379,109 ; v1@565.18,1008.82 ccw(c527,1047) 581,1047 ; v1(570,1004) 581,1015 581,1124 675,1218 675,1283 726,1334 975,1334 1009,1300 1175,1300 1225,1350 R2.1@1232,1350 ; v1@572.25,1001.75 ccw(c551.14,1022.86) 581,1022.86 ; 1194.64,1319.64 cw(c1245,1269.28) R2.1@1245,1340.5 ; 1211.71,1336.71 cw(c1245,1303.42) R2.1@1245,1350.5 ; 1241.25,356.25 cw(c1266,331.49) R34.1@1266,366.5 ; 1246.07,361.08 ccw(c1228.15,379) R34.1@1253.5,379 ; R34.1@1266,376 1266,381 994,109 379,109
VBUS_5V: C31.2 C34.2 C35.1 CN6.18 JP4.1 R29.1 U2.A4 U2.A9 U2.B4 U2.B9 U3.11 | length 6350
  Top Layer w10: v2@1259.5,3187.5 v2@1260,3188 ; U3.11@1407.84,3044.39 U3.11@1407.84,3052.39 ; U3.11@1408.53,3052.39 1408.53,3077.53 1425,3094 1440,3094 ; U3.11@1409.04,3068.54 cw(c1431.98,3068.54) 1415.76,3084.76 ; 1460,3094 1440,3094 ; C35.1@1553.5,3001 ccw(c1523.32,3001) 1544.66,3022.34 ccw(c1566,3043.68) C35.1@1566,3013.5 ; C35.1@1566,3001 1473,3094 1440,3094
  Top Layer w20: C31.2@1163,3157 1229,3157 v2@1259.5,3187.5 ; C31.2@1168.3,3151.7 cw(c1181.11,3138.89) 1181.11,3157 cw(c1181.11,3175.11) C31.2@1168.3,3162.3 ; 1242.76,3170.76 ccw(c1224.52,3189) v2@1250.32,3189 ; 1245.17,3173.17 cw(c1260,3158.35) v2@1260,3179.32 ; v2@1253.5,2430.5 1254,2430 1479,2430 1537.19,2488.19 2038.19,2488.19 v2(2071,2521) ; v2@1259.85,2424.15 cw(c1273.97,2410.03) 1273.97,2430 ; v2@1259.85,2437.85 ccw(c1278.8,2456.8) 1278.8,2430 ; v2@1494,3183.32 cw(c1494,3157.52) 1512.24,3175.76 ; v2@1496,3192 1519,3169 1566,3169 1566,3177 1611,3222 1691,3222 1735,3178 v2(1735,2910) 1649,2910 1566,2993 C35.1@1566,3001 ; v2@1503.68,3193 ccw(c1524.65,3193) 1509.83,3178.17 ; C34.2@1563.7,3163.7 ccw(c1550.89,3150.89) 1550.89,3169 ccw(c1550.89,3187.11) C34.2@1563.7,3174.3 ; C35.1@1573.5,3001 ccw(c1610.92,3001) 1584.46,2974.54 ; C34.2@1576.5,3169 cw(c1621.16,3169) 1589.58,3200.58 ; 1705.59,3207.41 cw(c1667.18,3169) R29.1@1721.5,3169 ; R29.1@1723.7,3163.7 cw(c1696.41,3136.41) 1735,3136.41 ; v2@1728.15,2903.15 ccw(c1711.62,2886.62) 1711.62,2910 ccw(c1711.62,2933.38) 1728.15,2916.85 ccw(c1711.62,2933.38) 1735,2933.38 ccw(c1758.38,2933.38) v2@1741.85,2916.85 ; v2@2061.31,2521 cw(c2037.93,2521) 2054.47,2504.47 cw(c2071,2487.93) v2@2071,2511.31
  Bottom Layer w10: U2.B9@1291.34,3246.41 1291.34,3297.34 1325,3331 1433,3331 1467.5,3296.5 U2.B4@1467.5,3250.41
  Bottom Layer w20: JP4.1@1224.32,1835.68 ccw(c1179.22,1880.78) 1243,1880.78 ccw(c1306.78,1880.78) JP4.1@1261.68,1835.68 ; JP4.1@1243,1817.24 1243,1945 1271,1973 1271,2128 1232,2167 1176,2167 1136,2207 1136,2343.46 1223.54,2431 v2(1253,2431) ; v2@1246.15,2424.15 ccw(c1229.62,2407.62) 1229.62,2431 ccw(c1229.62,2454.38) v2@1246.15,2437.85 ; v2@1260,3198.69 ccw(c1260,3222.07) 1276.53,3205.53 ccw(c1293.07,3189) v2@1269.69,3189 ; 1278.53,3207.53 1259,3188 1283.42,3212.42 ; U2.A4@1281.43,3233.61 cw(c1273.93,3226.12) U2.B9@1284.53,3226.12 ; 1284.53,3212.42 U2.B9@1284.53,3250.4 ; U2.B9@1284.53,3226.57 cw(c1294.48,3226.57) U2.B9@1287.45,3233.61 ; U2.B4@1470.4,3233.62 cw(c1463.34,3226.56) U2.B4@1473.32,3226.56 ; U2.B4@1473.32,3226.12 cw(c1483.92,3226.12) U2.A9@1476.43,3233.62 ; U2.B4@1473.32,3250.41 1473.32,3214.68 1496,3192 1479.32,3208.68 ; 1476.76,3211.24 cw(c1458.52,3193) v2@1484.32,3193 ; 1479.17,3208.83 ccw(c1494,3223.65) v2@1494,3202.68 ; v2@1734,2911 1912,2911 2072,2751 2072,2520 2112,2480 2652,2480 2685,2447 2685,1656 CN6.18@2628,1599 ; v2@1741.85,2903.15 cw(c1760.8,2884.2) 1760.8,2911 ; v2@1741.85,2916.85 ccw(c1755.97,2930.97) 1755.97,2911 ; v2@2064.15,2527.85 ccw(c2045.2,2546.8) 2072,2546.8 ; v2@2071,2511.31 cw(c2071,2487.93) 2087.53,2504.47 cw(c2104.07,2521) v2@2080.69,2521 ; 2072,2541.97 ccw(c2091.97,2541.97) v2@2077.85,2527.85 ; CN6.18@2628,1625.42 ccw(c2628,1689.19) 2673.1,1644.1 ccw(c2718.19,1599) CN6.18@2654.42,1599
  other v2: 1260,3189 1494,3193
VCC_3V3: CN1.20 CN1.24 CN2.2 CN2.4 JP5.1 R4.2 R12.2 | length 4721.3
  Top Layer w10: v1@1322,2147.19 cw(c1322,2130.75) 1333.63,2142.37 cw(c1345.25,2154) v1@1328.81,2154 ; v1(1322,2154) 1422,2054 1422,1773 JP5.1@1477,1718 ; 1423.5,1771.5 ccw(c1476.91,1824.91) JP5.1@1479.09,1749.4 ; 1428.49,1766.51 cw(c1379.98,1718) JP5.1@1448.58,1718 ; 1439.9,1755.1 ccw(c1477.83,1793.03) JP5.1@1479.38,1739.41 ; JP5.1@1445.56,1749.44 cw(c1414.12,1718) JP5.1@1458.58,1718
  Bottom Layer w10: CN1.24@248,1299 316,1299 ; CN1.20@248,1499 318,1499 ; CN1.20@264,1484.77 cw(c295.72,1456.55) 295.72,1499 cw(c295.72,1541.45) CN1.20@264,1513.23 ; CN1.24@264.31,1285.12 cw(c294.35,1259.55) 294.35,1299 cw(c294.35,1338.45) CN1.24@264.31,1312.88 ; CN1.20@271.47,1478.12 cw(c318,1436.73) 318,1499 ; CN1.20@271.47,1519.88 ccw(c318,1561.27) 318,1499 ; CN1.24@271.92,1278.64 cw(c316,1241.13) 316,1299 ; CN1.24@271.92,1319.36 ccw(c316,1356.87) 316,1299 ; CN2.4@406.78,1289.78 ccw(c353.15,1236.15) 353.15,1312 ccw(c353.15,1387.85) CN2.4@406.78,1334.22 ; CN2.2@406.78,1489.78 ccw(c353.15,1436.15) 353.15,1512 ccw(c353.15,1587.85) CN2.2@406.78,1534.22 ; CN2.4@413.86,1296.86 ccw(c377.29,1260.29) 377.29,1312 ccw(c377.29,1363.71) CN2.4@413.86,1327.14 ; CN2.2@413.86,1496.86 ccw(c377.29,1460.29) 377.29,1512 ccw(c377.29,1563.71) CN2.2@413.86,1527.14 ; CN2.4@427,1299 428,1300 CN2.4@436,1300 ; CN2.4@429,1312 329,1312 316,1299 ; CN2.2@429,1480.58 cw(c429,1404.73) 482.63,1458.37 cw(c536.27,1512) 460.42,1512 cw(c492.81,1512) 469.9,1534.9 ; CN2.2@429,1490.58 cw(c429,1438.88) 465.56,1475.44 cw(c502.12,1512) CN2.2@450.42,1512 ; CN2.4@431.86,1323.05 ccw(c441.63,1360.87) 469.25,1333.25 ; CN2.4@434.36,1332.74 ccw(c446.72,1380.53) 481.62,1345.62 ; CN2.4@436.86,1342.42 ccw(c451.8,1400.2) 494,1358 ; CN2.4@438.5,1302.5 494,1358 ; CN2.2@442.8,1528.38 ccw(c453.05,1540.55) 464.3,1529.3 ; CN2.2@449.24,1536.03 ccw(c460.09,1548.91) 472,1537 ; CN2.4@460.42,1312 cw(c490.4,1312) 469.2,1333.2 ; R12.2@1279,2197 v1(1322,2154) ; R12.2@1279,2218.5 ccw(c1279,2248.68) 1300.34,2227.34 ccw(c1321.68,2206) 1291.5,2206 ccw(c1343.41,2206) 1306.7,2169.3 ; R12.2@1281.5,2206 ccw(c1309.26,2206) 1289.63,2186.37 ; R12.2@1289,2216 R12.2@1279,2206 1315,2242 1390,2242 1442.5,2294.5 1442.5,2354.5 1510,2422 1610,2422 R4.2@1662,2370 ; v1@1315.19,2154 ccw(c1298.75,2154) 1310.37,2165.63 ccw(c1322,2177.25) v1@1322,2160.81 ; 1421.36,1652.27 ccw(c1355.62,1718) JP5.1@1448.58,1718 ; 1438.43,1669.34 ccw(c1389.76,1718) JP5.1@1458.58,1718 ; 1438.47,1669.38 cw(c1480,1627.85) JP5.1@1480,1686.58 ; JP5.1@1455.5,1686.41 ccw(c1423.91,1718) JP5.1@1468.58,1718 ; JP5.1@1455.54,1686.45 cw(c1480,1661.99) JP5.1@1480,1696.58 ; JP5.1@1477,1718 1477,1707.91 1306.09,1537 536,1537 472,1537 ; R4.2@1649.5,2370 ccw(c1619.32,2370) 1640.66,2391.34 ccw(c1662,2412.68) R4.2@1662,2382.5 ; 318,1499 331,1512 CN2.2@429,1512 ; CN2.2@429,1512 494,1447 494,1358 ; CN2.2@429,1512 447,1512 472,1537
VCC_5V: C26.2 CN1.26 CN2.5 JP4.2 JP4.4 JP4.6 R35.2 U5.3 | length 3439.2
  Top Layer w10: JP4.2@1243,1720 JP4.2@1269,1720
  Top Layer w20: 374.58,1266.42 392,1249 ; 374.58,1675.58 390.5,1691.5 ; 402.35,1703.35 ccw(c380.69,1725) v2@411.32,1725 ; v2@421,1722 390.5,1691.5 ; CN2.5@423,1228.58 423,1218 CN2.5@429,1212 392,1249 ; JP4.6@1043,1720 1143,1720 JP4.2@1243,1720 ; JP4.6@1061.68,1698.32 cw(c1114.02,1645.98) JP4.4@1114.02,1720 ; JP4.6@1061.68,1735.68 ccw(c1099.53,1773.53) 1099.53,1720 ; JP4.6@1071.98,1720 cw(c1071.98,1645.98) JP4.4@1124.32,1698.32 ; 1086.47,1720 ccw(c1086.47,1773.53) JP4.4@1124.32,1735.68 ; JP4.4@1161.68,1698.32 cw(c1214.02,1645.98) JP4.2@1214.02,1720 ; JP4.4@1161.68,1735.68 ccw(c1199.53,1773.53) 1199.53,1720 ; JP4.4@1171.98,1720 cw(c1171.98,1645.98) JP4.2@1224.32,1698.32 ; 1186.47,1720 ccw(c1186.47,1773.53) JP4.2@1224.32,1735.68 ; 390.5,1691.5 372.58,1673.58 372.58,1268.42 392,1249
  Bottom Layer w10: CN2.5@427,1199 CN2.5@428,1200 ; JP4.6@1038,1725 JP4.6@1043,1720 ; JP4.6@1040.24,1717.24 JP4.6@1043,1717.24 ; JP4.2@1243,1720 1257,1720 1305,1768 ; JP4.2@1244.44,1728.33 ccw(c1249.25,1766.08) 1276.17,1739.17 ; JP4.2@1245.71,1738.25 ccw(c1252.51,1791.65) 1290.58,1753.58 ; JP4.2@1246.97,1748.17 ccw(c1255.77,1817.22) 1305,1768 ; JP4.2@1274.42,1717 cw(c1323.71,1717) 1288.85,1751.85 ; 1305,1954.36 cw(c1396.64,1954.36) R35.2@1331.84,2019.16 ; 1305,1978.51 cw(c1372.49,1978.51) R35.2@1324.77,2026.23 ; 1305,2002.65 cw(c1348.35,2002.65) R35.2@1317.7,2033.3 ; R35.2@1323,2028 1322,2028 1305,2011 1305,1768 ; U5.3@1528.45,1933.95 U5.3@1528.45,1955.55
  Bottom Layer w20: CN1.26@248,1199 317,1199 330,1212 CN2.5@429,1212 ; CN1.26@266.68,1180.32 cw(c311.78,1135.22) 311.78,1199 cw(c311.78,1262.78) CN1.26@266.68,1217.68 ; CN2.5@410.32,1193.32 ccw(c365.22,1148.22) 365.22,1212 ccw(c365.22,1275.78) CN2.5@410.32,1230.68 ; v2(421,1725) 822,1725 866,1681 1004,1681 JP4.6@1040.24,1717.24 ; v2@427.85,1718.15 cw(c444.38,1701.62) 444.38,1725 cw(c444.38,1748.38) v2@427.85,1731.85 ; R35.2@1323,2028 1418,2028 1456,2028 U5.3@1528.45,1955.55 ; R35.2@1328.3,2022.7 cw(c1341.11,2009.89) 1341.11,2028 cw(c1341.11,2046.11) R35.2@1328.3,2033.3 ; C26.2@1407.7,2022.7 ccw(c1394.89,2009.89) 1394.89,2028 ccw(c1394.89,2046.11) C26.2@1407.7,2033.3 ; C26.2@1418.3,2022.7 cw(c1431.11,2009.89) 1431.11,2028 cw(c1431.11,2046.11) C26.2@1418.3,2033.3 ; U5.3@1507.9,1976.1 cw(c1486.42,1954.62) U5.3@1516.8,1954.62 ; U5.3@1510.14,1973.86 ccw(c1528.45,1992.17) U5.3@1528.45,1966.28
VCC_MCU: C1.2 C3.2 C16.1 C18.1 CN1.13 JP1.2 JP6.1 P1.1 R1.2 R3.2 R13.2 R31.1 U1.12 U1.50 | length 8464.7
  Top Layer w10: v1(288,1850) 317,1879 317,1946 v1@361,1990 ; v1@288,1856.81 ccw(c288,1873.25) 299.63,1861.63 ccw(c311.25,1850) v1@294.81,1850 ; 348.67,1977.67 ccw(c335.33,1991) v1@354.19,1991 ; 351.08,1980.08 cw(c361,1970.16) v1@361,1984.19 ; 461,3157 P1.1@350,3157 519,3157 712,2964 ; 712,2901 712,2889 ; 717,2215 739.5,2192.5 ; v1@759.19,2166 ccw(c742.75,2166) 754.37,2177.63 ccw(c766,2189.25) v1@766,2172.81 ; v1@766,2159.19 cw(c766,2142.75) 777.63,2154.37 cw(c789.25,2166) v1@772.81,2166 ; R31.1@798.16,2991.16 ccw(c776.82,2969.82) 776.82,3000 ccw(c776.82,3030.18) R31.1@798.16,3008.84 ; R31.1@807,3000 746,3000 712,2966 712,2964 ; U1.12@1120.61,976 v1(1218,976) ; v1@1213.18,971.18 ccw(c1201.56,959.56) 1201.56,976 ccw(c1201.56,992.44) v1@1213.18,980.82 ; JP1.2@1331.58,1818 ccw(c1255.73,1818) 1309.37,1871.63 ccw(c1363,1925.27) JP1.2@1363,1849.42 ; JP1.2@1341.58,1818 ccw(c1289.88,1818) 1326.44,1854.56 ccw(c1363,1891.12) JP1.2@1363,1839.42 ; JP1.2@1363,1818 1240,1941 1125,1941 972,2094 838,2094 v1(766,2166) 739.5,2192.5 ; U1.50@1637.86,996.16 1684.84,996.16 v1(1696,985) ; v1@1784.18,967.82 ccw(c1772.56,979.44) 1789,979.44 ccw(c1805.44,979.44) 1793.82,967.82 ccw(c1805.44,979.44) 1805.44,963 ccw(c1805.44,946.56) v1@1793.82,958.18 ; v1(1789,963) 1789,1039 1888,1138 1888,1187 1946,1245 ; v1@1790,963 v1(1905,963) ; v1@1869.18,1734.18 cw(c1857.56,1722.56) 1874,1722.56 cw(c1890.44,1722.56) v1@1878.82,1734.18 ; v1(1874,1739) 1874,1608 1963,1519 1963,1262 1946,1245 ; v1@1900.18,958.18 ccw(c1888.56,946.56) 1888.56,963 ccw(c1888.56,979.44) v1@1900.18,967.82 ; 1960,1259 1946,1245 ; 380.18,3157 ccw(c380.18,3126.82) 358.84,3148.16 cw(c380.18,3126.82) 380.18,3157 ; 380.18,3157 cw(c380.18,3187.18) 358.84,3165.84 ccw(c380.18,3187.18) 380.18,3157 ; 404.32,3157 ccw(c404.32,3102.68) 365.91,3141.09 cw(c404.32,3102.68) 404.32,3157 ; 404.32,3157 cw(c404.32,3211.32) 365.91,3172.91 ccw(c404.32,3211.32) 404.32,3157 ; 712,2889 712,2220 739.5,2192.5 ; 712,2889 712,2964
  Bottom Layer w10: CN1.13@148,1799 198.58,1849.58 ; CN1.13@148.91,1820.4 ccw(c150.8,1865.16) 182.48,1833.48 ccw(c214.16,1801.8) CN1.13@169.4,1799.91 ; CN1.13@149.33,1830.39 ccw(c152.11,1896.05) 198.58,1849.58 ; CN1.13@179.39,1800.33 cw(c245.05,1803.11) 198.58,1849.58 ; 270.55,1849.58 ccw(c270.55,1867.45) v1@283.18,1854.82 ; 272.56,1849.58 cw(c272.56,1834.56) v1@283.18,1845.18 ; v1@287,1849.58 198.58,1849.58 ; v1@358.75,1993.25 cw(c379.86,1972.14) 379.86,2002 ; v1@361,1990 373,2002 ; v1@361.55,1997.79 ccw(c362.72,2012.28) 373,2002 ; v1@365.82,1986.18 cw(c404,1948) 404,2002 ; v1@367.81,1991 cw(c381.84,1991) 371.92,2000.92 ; v1@759.19,2166 cw(c742.75,2166) 754.37,2154.37 cw(c766,2142.75) v1@766,2159.19 ; v1(766,2166) 602,2002 373,2002 ; v1@1222.82,971.18 cw(c1234.44,959.56) 1234.44,976 cw(c1234.44,992.44) v1@1222.82,980.82 ; 1239.78,976 cw(c1239.78,942.61) C3.2@1265.1,964.37 ; C3.2@1257.52,957.85 ccw(c1218,923.9) v1(1218,976) 1257,976 C3.2@1267,966 C1.2@1267,884 1267,872 1327,812 R3.2@1327,802 ; C1.2@1258.16,892.84 ccw(c1236.82,914.18) 1267,914.18 ccw(c1297.18,914.18) C1.2@1275.84,892.84 ; C3.2@1258.16,957.16 cw(c1236.82,935.82) 1267,935.82 cw(c1297.18,935.82) C3.2@1275.84,957.16 ; C3.2@1267,973 1302,1008 1355,1008 1377,1030 1382,1030 ; C3.2@1267,978.5 ccw(c1267,991.78) C3.2@1276.39,982.39 ; C1.2@1269.5,884 ccw(c1304.5,884) 1279.75,859.25 ; C3.2@1269.5,966 cw(c1292.43,966) C3.2@1276.22,982.22 ; C1.2@1279.5,884 ccw(c1338.64,884) 1296.82,842.18 ; C3.2@1279.5,966 cw(c1326.58,966) 1293.29,999.29 ; 1298.59,840.41 cw(c1260.18,802) R3.2@1314.5,802 ; 1315.66,823.34 cw(c1294.32,802) R3.2@1324.5,802 ; R1.2@1341,1340.5 cw(c1341,1317.56) 1357.22,1333.78 ; R1.2@1341,1350 1375,1316 1375,1037 1382,1030 ; R1.2@1353.5,1353 ccw(c1390.92,1353) 1364.46,1326.54 ; JP1.2@1364,1819 1365,1818 JP1.2@1363,1818 1412.42,1768.58 ; JP1.2@1364.28,1796.62 cw(c1366.79,1754.42) 1396.69,1784.31 cw(c1426.58,1814.21) JP1.2@1384.38,1816.72 ; JP1.2@1364.87,1786.64 cw(c1368.56,1724.73) 1412.42,1768.58 ; JP1.2@1394.36,1816.13 ccw(c1456.27,1812.44) 1412.42,1768.58 ; JP6.1@1562.83,1754.17 cw(c1531.58,1722.93) JP6.1@1575.64,1719.61 ; JP6.1@1564.28,1752.72 ccw(c1596.4,1784.85) JP6.1@1596.81,1739.42 ; JP6.1@1565.67,1720.36 ccw(c1502.93,1725.09) 1547.42,1769.58 ccw(c1596.11,1818.27) JP6.1@1596.72,1749.42 ; JP6.1@1602.2,1697.22 cw(c1608.41,1672.39) JP6.1@1626.51,1690.49 ; JP6.1@1604.62,1687.52 cw(c1613.4,1652.41) 1639,1678 cw(c1667,1706.01) JP6.1@1627.97,1712.7 ; JP6.1@1618.11,1714.38 ccw(c1643.67,1710) JP6.1@1625.33,1691.67 ; v1@1689.19,985 ccw(c1672.75,985) 1684.37,996.63 ccw(c1696,1008.25) v1@1696,991.81 ; v1@1696,978.19 cw(c1696,961.75) 1707.63,973.37 cw(c1719.25,985) v1@1702.81,985 ; C18.1@1738.47,951.91 ccw(c1721,937.1) 1721,960 ; C18.1@1738.47,968.09 cw(c1721,982.9) 1721,960 ; C18.1@1756.84,951.16 cw(c1785.42,922.58) v1@1785.42,963 ; C18.1@1756.84,968.84 ccw(c1770.93,982.93) 1770.93,963 ; v1@1784.18,958.18 ccw(c1772.56,946.56) 1772.56,963 ccw(c1772.56,979.44) v1@1784.18,967.82 ; v1@1793.58,963 cw(c1793.58,922.58) C16.1@1822.16,951.16 ; v1@1793.82,958.18 cw(c1805.44,946.56) 1805.44,963 cw(c1805.44,979.44) v1@1793.82,967.82 ; 1808.07,963 ccw(c1808.07,982.93) C16.1@1822.16,968.84 ; C16.1@1831,960 1828,963 v1(1789,963) 1751,963 C18.1@1748,960 1721,960 ; v1@1867.19,1739 ccw(c1850.75,1739) 1862.37,1750.63 ccw(c1874,1762.25) v1@1874,1745.81 ; v1(1874,1739) 1850,1763 1807,1763 1723,1679 1638,1679 1548.42,1768.58 1412.42,1768.58 ; v1@1909.82,958.18 cw(c1921.44,946.56) 1921.44,963 cw(c1921.44,979.44) v1@1909.82,967.82 ; v1@1913.07,963 ccw(c1913.07,982.93) R13.2@1927.16,968.84 ; R13.2@1926,952.5 ccw(c1905,936.75) v1(1905,963) 1933,963 R13.2@1936,960 ; 1382,1030 1443.5,1030 1477.5,1064 1617,1064 v1(1696,985) 1721,960
  other v1: 361,1991
VCORE: C4.1 C9.1 U1.10 | length 388.3
  Top Layer w10: U1.10@1127,1016 1228,1016 v1(1229,1017) ; 1210.14,1016 ccw(c1210.14,1035.86) v1@1224.18,1021.82 ; 1214.97,1016 cw(c1214.97,1002.97) v1@1224.18,1012.18
  Bottom Layer w10: v1(1229,1017) 1231,1017 C9.1@1267,1053 ; v1@1229,1023.81 ccw(c1229,1045.08) 1244.04,1030.04 ; v1@1235.81,1017 cw(c1247.43,1017) 1239.21,1025.21 ; v1@1237.13,1023.13 cw(c1267,993.26) C9.1@1267,1035.5 ; 1249.19,1035.19 ccw(c1236.39,1048) C9.1@1254.5,1048
  Bottom Layer w20: C9.1@1261.7,1053.3 ccw(c1248.89,1066.11) 1267,1066.11 ccw(c1285.11,1066.11) C9.1@1272.3,1053.3 ; C4.1@1261.7,1124.7 cw(c1248.89,1111.89) 1267,1111.89 cw(c1285.11,1111.89) C4.1@1272.3,1124.7 ; C9.1@1267,1053 C4.1@1267,1130
VDD_LINK: C20.2 C21.2 C29.1 C32.1 D5.2 D5.4 R30.1 R31.2 U3.12 U3.13 U3.20 U3.31 | length 3265.4
  Top Layer w10: R31.2@867,3000 900,3033 1043.91,3033 1121.91,2955 C29.1@1163,2955 ; R31.2@867,3012.5 ccw(c867,3042.68) 888.34,3021.34 ccw(c909.68,3000) R31.2@879.5,3000 ; C29.1@1154.16,2946.16 ccw(c1132.82,2924.82) 1132.82,2955 ccw(c1132.82,2985.18) C29.1@1154.16,2963.84 ; C29.1@1163,2962 v1(1201,2962) ccw(c1201,2927.73) C29.1@1173.16,2947.71 ; C29.1@1165.03,2953.54 cw(c1181.51,2941.71) 1181.51,2962 ; v1@1196.18,2957.18 ccw(c1184.56,2945.56) 1184.56,2962 ccw(c1184.56,2978.44) v1@1196.18,2966.82 ; v1@1201,2961.84 U3.20@1278.61,2961.84 ; v1@1205.82,2957.18 cw(c1217.06,2945.94) 1217.06,2961.84 ; v1@1205.82,2966.82 ccw(c1217.82,2978.82) 1217.82,2961.84 ; C21.2@1369,2764 1459,2764 v1@1459,2793 ; U3.13@1369.16,3052.39 1369.16,3089.16 1376,3096 ; 1370.5,3090.5 cw(c1381.75,3079.25) v1@1388.23,3093.78 ; 1378.63,3098.63 cw(c1389.78,3087.48) v1@1391.31,3103.17 ; C21.2@1382.84,2754.16 cw(c1406.59,2730.41) 1406.59,2764 ; C21.2@1382.84,2771.84 ccw(c1401.76,2790.76) 1401.76,2764 ; v1@1384.54,3102.15 cw(c1376,3105) 1376,3096 ; U3.12@1388.84,3052.39 v1@1388.84,3093.84 ; 1388.84,3078.35 cw(c1412.65,3078.35) v1@1395.82,3095.18 ; v1@1391,3096 1376,3096 ; v1@1391,3106.81 ccw(c1391,3128.08) 1406.04,3113.04 ; v1@1392,3099 1422,3129 1521,3129 1564,3086 C32.1@1566,3086 ; v1@1397.81,3100 cw(c1409.43,3100) 1401.21,3108.21 ; U3.31@1428.21,2851.61 1428.21,2823.79 v1(1451,2801) v1@1459,2793 ; 1429.41,2764 cw(c1429.41,2730.41) C20.2@1453.16,2754.16 ; 1434.24,2764 ccw(c1434.24,2790.76) 1453.16,2771.84 ccw(c1439.07,2785.93) 1459,2785.93 ; v1@1444.19,2801 ccw(c1427.75,2801) 1439.37,2812.63 ccw(c1451,2824.25) v1@1451,2807.81 ; v1@1446.18,2796.18 cw(c1415.24,2765.24) C20.2@1459,2765.24 ; v1@1453.25,2803.25 cw(c1439.38,2789.38) 1459,2789.38 ; C20.2@1469.23,2773.19 cw(c1483.28,2793) v1@1459,2793 ; 1542.96,3107.04 ccw(c1566,3130.09) C32.1@1566,3097.5 ; 1545.37,3104.63 cw(c1525.73,3085) C32.1@1553.5,3085 ; C32.1@1557.16,3076.16 cw(c1533.41,3052.41) v1@1567,3052.41 ; v1@1562.18,3056.82 ccw(c1550.56,3068.44) 1567,3068.44 ccw(c1583.44,3068.44) v1@1571.82,3056.82 ; v1(1567,3052) C32.1@1567,3085 ; v1@1567,3057.24 cw(c1593.76,3057.24) C32.1@1574.84,3076.16 ; v1(2167,3182) 2192.06,3182 D5.2@2226,3148.06 ; v1@2171.82,3177.18 cw(c2183.44,3165.56) 2183.44,3182 cw(c2183.44,3198.44) v1@2171.82,3186.82 ; 2207.65,3166.4 ccw(c2226,3184.75) D5.2@2226,3158.8 ; D5.2@2214.78,3159.27 cw(c2206.51,3151.01) D5.2@2218.2,3151.01
  Bottom Layer w10: v1@1196.18,2966.82 ccw(c1184.56,2978.44) 1201,2978.44 ccw(c1217.44,2978.44) v1@1205.82,2966.82 ; v1(1201,2962) 1201,2981 1240,3020 1365,3020 1391,3046 v1(1391,3100) ; v1@1386.18,3095.18 cw(c1374.56,3083.56) 1391,3083.56 cw(c1407.44,3083.56) v1@1395.82,3095.18 ; v1@1451,2800 1479,2828 1479,3014 1517,3052 v1(1567,3052) ; v1@1451,2807.81 ccw(c1451,2826.67) 1464.33,2813.33 ; v1@1457.81,2801 cw(c1471.84,2801) 1461.92,2810.92 ; R30.1@1556.55,3028.21 ccw(c1534.7,3052) v1(1567,3052) ; v1@1562.18,3056.82 cw(c1550.56,3068.44) 1550.56,3052 cw(c1550.56,3035.56) 1562.18,3047.18 cw(c1550.55,3035.55) 1567,3035.55 cw(c1583.44,3035.56) 1571.82,3047.18 cw(c1583.44,3035.56) 1583.44,3052 cw(c1583.44,3068.44) v1@1571.82,3056.82 ; R30.1@1567,3019 v1(1567,3052) ; v1@1567,3044.35 ccw(c1590.35,3044.35) R30.1@1573.84,3027.84 ; v1@2162.18,3177.18 ccw(c2150.56,3165.56) 2150.56,3182 ccw(c2150.56,3198.44) v1@2162.18,3186.82 ; v1(2167,3182) 2110,3182 1980,3052 v1(1567,3052)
